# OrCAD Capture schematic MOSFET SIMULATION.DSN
size A
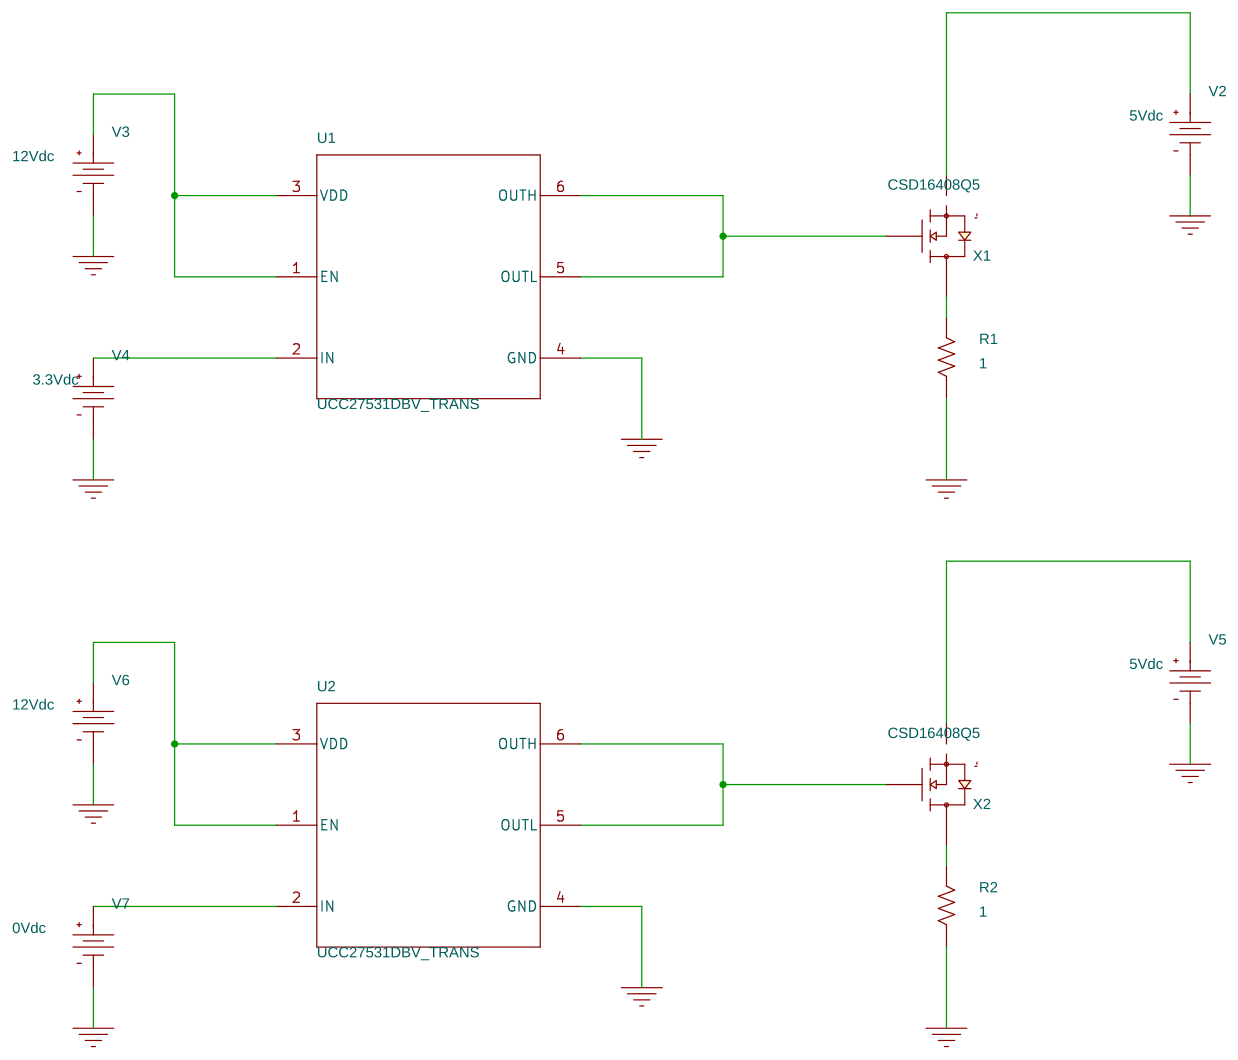
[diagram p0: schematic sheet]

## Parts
R1  1  [AX/RC05]
R2  1  [AX/RC05]
U1  UCC27531DBV_TRANS  [DBV0006A_N]
U2  UCC27531DBV_TRANS  [DBV0006A_N]
V2  VDC
V3  VDC
V4  VDC
V5  VDC
V6  VDC
V7  VDC
X1  CSD16408Q5
X2  CSD16408Q5

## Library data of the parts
R1 R2 = R
U1 U2 = UCC27531DBV_TRANS
V2 V5 = VDC: DC: 5Vdc
V3 V6 = VDC: DC: 12Vdc
V4 = VDC: DC: 3.3Vdc
V7 = VDC: DC: 0Vdc
X1 = csd16408q5_1
X2 = csd16408q5

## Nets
0: R1.1 R2.1 U1.4(GND) U2.4(GND) V2.1(-) V3.1(-) V4.1(-) V5.1(-) V6.1(-) V7.1(-)
N00146: V2.0(+) X1.source
N02481: R1.2 X1.drain
N02642: U1.5(OUTL) U1.6(OUTH) X1.gate
N02923: U1.1(EN) U1.3(VDD) V3.0(+)
N03092: U1.2(IN) V4.0(+)
N03535: V5.0(+) X2.source
N03623: R2.2 X2.drain
N03629: U2.5(OUTL) U2.6(OUTH) X2.gate
N03687: U2.1(EN) U2.3(VDD) V6.0(+)
N03789: U2.2(IN) V7.0(+)
